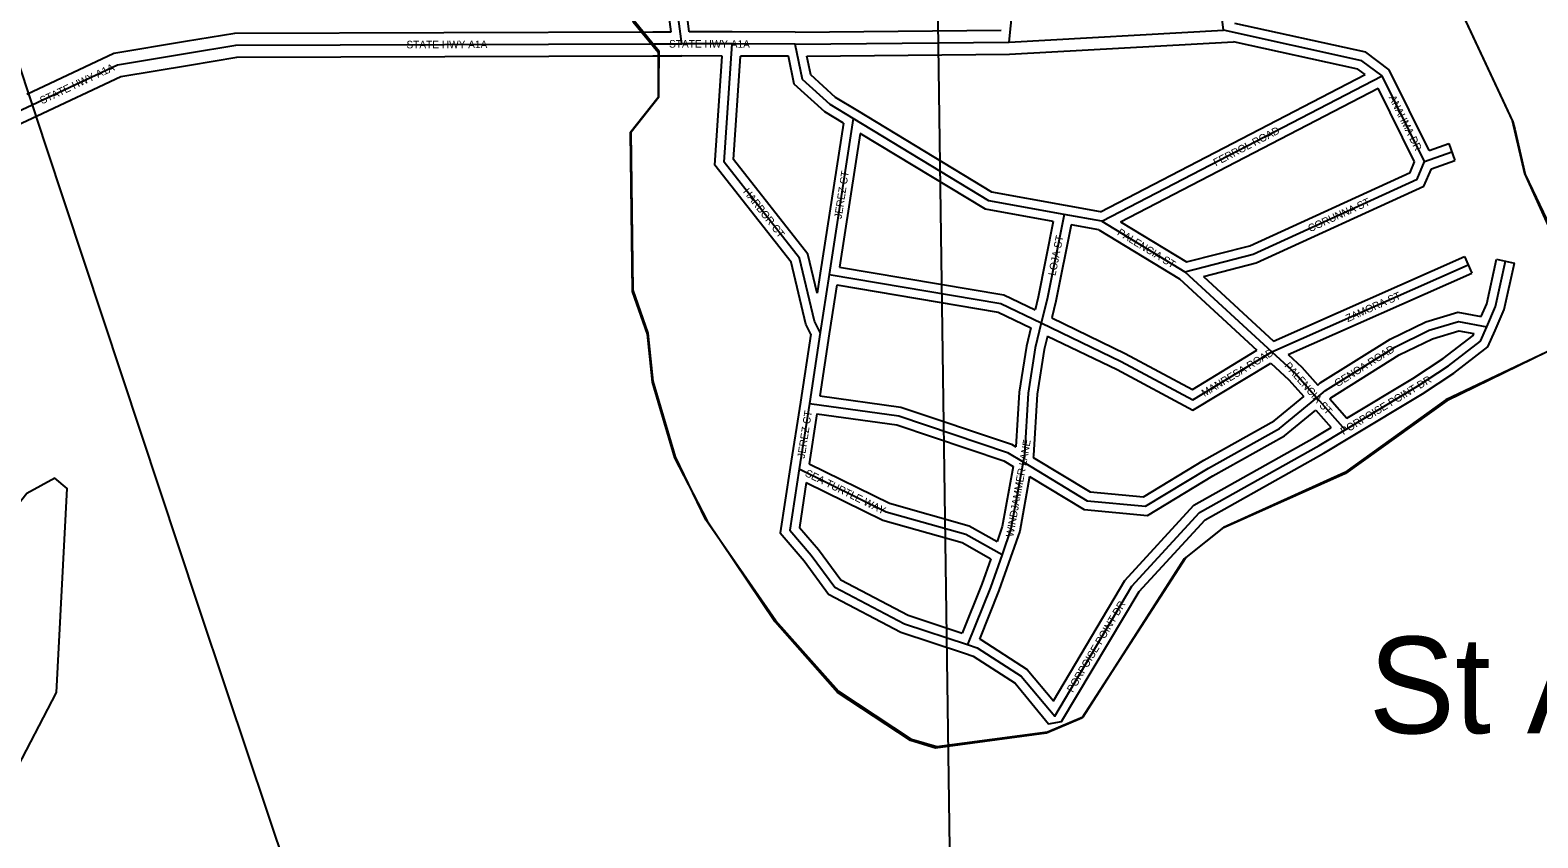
# Model space of a CAD drawing. Extents: x 418523 to 616617, y 1878279 to 2196743.
# Drawn here: x 559594 to 564582, y 2027177 to 2029851 of the extents above; entities that cross this region are included whole.
import ezdxf

# ---------------------------------------------------------------- set-up
doc = ezdxf.new("R2010")
doc.units = 0
for name, color, linetype in [('Level 1', 7, 'Continuous'), ('Level 22', 7, 'Continuous'), ('Level 23', 7, 'Continuous'), ('Level 31', 7, 'Continuous'), ('Level 32', 7, 'Continuous'), ('Level 34', 7, 'Continuous'), ('Level 41', 7, 'Continuous'), ('Level 5', 7, 'Continuous'), ('Level 8', 7, 'Continuous')]:
    doc.layers.add(name, color=color, linetype=linetype)

msp = doc.modelspace()

# ---------------------------------------------------------------- linework, layer by layer
at = {"layer": 'Level 1'}
msp.add_line((562655.833, 2025828.258), (562597.423, 2029956.365), dxfattribs=at)
at = {"layer": 'Level 22'}
for p, q in [((561654.286, 2029805.851), (561749.649, 2029805.97)), ((561916.295, 2029805.539), (561749.649, 2029805.97)), ((562124.76, 2029805.001), (561916.295, 2029805.539)), ((562124.76, 2029805.001), (562833.185, 2029811.549)), ((562833.185, 2029811.549), (563542.01, 2029851.203)), ((559517.02, 2029564.881), (559599.812, 2029603.574))]:
    msp.add_line(p, q, dxfattribs=at)
for points in [[(563542.01, 2029851.203), (563509.44, 2030126.578), (563443.099, 2030326.761)], [(560113.829, 2029774.958), (560273.893, 2029801.812), (561654.286, 2029805.851)], [(559599.812, 2029603.574), (559882.132, 2029736.293), (560113.829, 2029774.958)]]:
    msp.add_lwpolyline(points, dxfattribs=at)
at = {"layer": 'Level 23'}
for p, q in [((561654.237, 2029845.851), (561714.302, 2029845.926)), ((561916.398, 2029845.539), (561774.793, 2029845.905)), ((562124.864, 2029845.001), (561916.398, 2029845.539)), ((562124.864, 2029845.001), (562806.954, 2029851.308)), ((562834.489, 2029771.557), (563575.761, 2029813.026)), ((561654.336, 2029765.851), (561749.546, 2029765.969)), ((561883.575, 2029765.621), (561749.546, 2029765.969)), ((562102.552, 2029765.057), (561943.698, 2029765.466)), ((562163.82, 2029765.359), (562834.489, 2029771.558)), ((559533.956, 2029528.641), (559616.75, 2029567.335))]:
    msp.add_line(p, q, dxfattribs=at)
for points in [[(559582.795, 2029639.775), (559870.106, 2029774.841), (560107.245, 2029814.413)], [(560107.21, 2029814.407), (560270.502, 2029841.803), (561654.169, 2029845.853)], [(560120.447, 2029735.509), (560277.284, 2029761.821), (561654.404, 2029765.851)], [(559616.83, 2029567.373), (559894.159, 2029697.746), (560120.413, 2029735.503)]]:
    msp.add_lwpolyline(points, dxfattribs=at)
at = {"layer": 'Level 31'}
for p, q in [((562833.185, 2029811.549), (562867.66, 2030161.668)), ((563140.26, 2029218.724), (564066.914, 2029699.683)), ((564207.82, 2029416.036), (564066.914, 2029699.683)), ((562317.071, 2029558.308), (562237.809, 2029042.111)), ((564207.82, 2029416.036), (564297.878, 2029448.176)), ((563140.26, 2029218.724), (563014.539, 2029241.227)), ((563140.26, 2029218.724), (563414.84, 2029051.468)), ((563702.165, 2028786.358), (564352.385, 2029074.557)), ((562237.809, 2029042.111), (562208.168, 2028849.81)), ((563414.84, 2029051.468), (563702.165, 2028786.358)), ((562208.168, 2028849.81), (562172.08, 2028614.613)), ((562172.08, 2028614.613), (562138.574, 2028398.321)), ((563850.691, 2028634.336), (563944.522, 2028527.909))]:
    msp.add_line(p, q, dxfattribs=at)
for points in [[(561749.649, 2029805.97), (561725.115, 2029998.046), (561492.915, 2030498.683), (561459.887, 2030590.412), (561468.276, 2030648.94)], [(562208.168, 2028849.81), (562188.939, 2028888.044), (562139.415, 2029096.55), (561890.258, 2029413.941), (561916.295, 2029805.539)], [(562317.071, 2029558.308), (562240.835, 2029604.689), (562149.489, 2029688.202), (562124.76, 2029805.001)], [(564066.914, 2029699.683), (564000.191, 2029750.037), (563542.01, 2029851.203)], [(563014.539, 2029241.227), (562765.314, 2029286.595), (562317.071, 2029558.308)], [(563414.84, 2029051.468), (563639.932, 2029109.084), (564182.644, 2029357.549), (564207.82, 2029416.036)], [(563014.539, 2029241.227), (562958.38, 2028960.623), (562939.487, 2028881.757)], [(564413.334, 2028868.935), (564442.651, 2028936.139), (564475.342, 2029086.249)], [(562237.809, 2029042.111), (562805.95, 2028946.466), (562939.487, 2028881.757)], [(562939.487, 2028881.757), (562919.634, 2028799.256), (562895.805, 2028649.125), (562883.567, 2028446.596), (562879.068, 2028421.516)], [(562939.487, 2028881.757), (563203.714, 2028754.166), (563440.38, 2028627.374), (563702.165, 2028786.358)], [(563850.691, 2028634.336), (563879.901, 2028658.626), (564108.695, 2028802.06), (564222.892, 2028857.412), (564319.598, 2028886.626), (564413.334, 2028868.935)], [(563944.522, 2028527.909), (564184.409, 2028672.406), (564286.913, 2028739.789), (564392.623, 2028821.711), (564413.334, 2028868.935)], [(563702.165, 2028786.358), (563780.241, 2028714.519), (563850.691, 2028634.336)], [(562172.08, 2028614.613), (562468.21, 2028573.85), (562827.82, 2028452.557), (562879.068, 2028421.516)], [(562879.068, 2028421.516), (563091.019, 2028293.329), (563284.24, 2028275.018), (563492.401, 2028401.044), (563727.188, 2028532.458), (563850.691, 2028634.336)], [(562694.713, 2027816.853), (562726.686, 2027806.225), (562872.825, 2027712.026), (562983.698, 2027579.371), (563239.53, 2028010.749), (563462.881, 2028254.199), (563858.848, 2028476.486), (563944.522, 2028527.909)], [(562879.068, 2028421.516), (562838.899, 2028199.784), (562809.534, 2028114.761)], [(562138.574, 2028398.321), (562107.005, 2028195.842), (562178.395, 2028112.742)], [(562138.574, 2028398.321), (562426.21, 2028256.481), (562689.625, 2028182.346), (562809.534, 2028114.761)], [(562178.395, 2028112.742), (562255.75, 2028007.446), (562486.729, 2027886.116), (562694.713, 2027816.853)], [(562809.534, 2028114.761), (562771.236, 2028006.125), (562694.713, 2027816.853)]]:
    msp.add_lwpolyline(points, dxfattribs=at)
at = {"layer": 'Level 32'}
for p, q in [((563135.5, 2029250.053), (564010.869, 2029704.393)), ((564222.833, 2029453.247), (564090.635, 2029719.366)), ((563201.36, 2029216.635), (564053.631, 2029658.987)), ((564174.77, 2029415.133), (564053.631, 2029658.987)), ((562284.381, 2029543.08), (562208.156, 2029046.664)), ((562339.911, 2029509.381), (562271.951, 2029066.786)), ((564222.833, 2029453.246), (564287.795, 2029476.43)), ((564287.795, 2029476.43), (564307.962, 2029419.92)), ((564230.21, 2029392.171), (564307.962, 2029419.92)), ((563135.5, 2029250.053), (563019.825, 2029270.758)), ((563129.449, 2029190.181), (563038.188, 2029206.516)), ((563201.36, 2029216.634), (563419.651, 2029083.666)), ((563129.449, 2029190.181), (563396.688, 2029027.397)), ((563708.026, 2028821.771), (564340.229, 2029101.985)), ((564340.229, 2029101.985), (564364.543, 2029047.13)), ((564446.029, 2029092.633), (564504.655, 2029079.865)), ((562208.159, 2029046.681), (562197.902, 2028980.133)), ((562262.826, 2029007.476), (562237.819, 2028845.239)), ((563396.689, 2029027.396), (563652.545, 2028791.322)), ((563475.748, 2029036.09), (563708.025, 2028821.77)), ((563756.14, 2028777.465), (564364.543, 2029047.13)), ((562177.062, 2028844.889), (562142.426, 2028619.163)), ((562237.822, 2028845.259), (562206.355, 2028640.178)), ((562142.433, 2028619.206), (562108.927, 2028402.912)), ((563893.617, 2028631.013), (563950.478, 2028566.519)), ((562197.211, 2028580.869), (562171.593, 2028415.488)), ((563847.388, 2028592.718), (563898.195, 2028535.091))]:
    msp.add_line(p, q, dxfattribs=at)
for points in [[(561714.302, 2029845.926), (561695.945, 2029989.637), (561465.14, 2030487.267), (561429.13, 2030587.276), (561441.239, 2030671.751)], [(561774.793, 2029845.905), (561754.285, 2030006.455), (561520.69, 2030510.099), (561490.643, 2030593.549), (561495.315, 2030626.127)], [(564090.635, 2029719.367), (564013.045, 2029777.922), (563579.639, 2029873.617)], [(564010.868, 2029704.393), (563987.338, 2029722.152), (563575.761, 2029813.026)], [(562177.062, 2028844.889), (562160.561, 2028877.698), (562111.75, 2029083.207), (561859.56, 2029404.46), (561883.575, 2029765.621)], [(562197.902, 2028980.133), (562167.082, 2029109.892), (561920.955, 2029423.423), (561943.698, 2029765.466)], [(562284.381, 2029543.079), (562222.748, 2029580.576), (562122.135, 2029672.562), (562102.552, 2029765.057)], [(562332.665, 2029583.938), (562258.923, 2029628.801), (562176.844, 2029703.842), (562163.82, 2029765.358)], [(563019.912, 2029270.743), (562776.132, 2029315.119), (562332.623, 2029583.963)], [(562979.13, 2029217.179), (562754.495, 2029258.071), (562339.911, 2029509.381)], [(563419.65, 2029083.666), (563629.888, 2029137.481), (564159.654, 2029380.02), (564174.77, 2029415.134)], [(563475.748, 2029036.09), (563649.976, 2029080.686), (564205.634, 2029335.079), (564230.21, 2029392.171)], [(562979.131, 2029217.179), (562929.073, 2028967.064), (562919.002, 2028925.021)], [(563038.188, 2029206.516), (562987.686, 2028954.183), (562974.292, 2028898.265)], [(562271.951, 2029066.786), (562815.167, 2028975.338), (562919.002, 2028925.021)], [(564395.399, 2028902.85), (564413.968, 2028945.418), (564446.029, 2029092.633)], [(564440.832, 2028856.939), (564471.335, 2028926.859), (564504.655, 2029079.865)], [(562262.827, 2029007.476), (562796.735, 2028917.595), (562904.668, 2028865.291)], [(563853.959, 2028676.07), (563862.264, 2028682.978), (564094.142, 2028828.346), (564211.943, 2028885.445), (564317.949, 2028917.467), (564395.399, 2028902.85)], [(562904.669, 2028865.292), (562890.189, 2028805.126), (562865.947, 2028652.389), (562854.997, 2028471.171)], [(562974.292, 2028898.265), (563217.325, 2028780.908), (563439.448, 2028661.908), (563652.545, 2028791.322)], [(563960.002, 2028502.211), (564200.395, 2028647.011), (564304.368, 2028715.361), (564417.032, 2028802.672), (564440.808, 2028856.885)], [(562959.95, 2028838.56), (562949.079, 2028793.386), (562925.664, 2028645.861), (562913.407, 2028443.03), (562912.24, 2028436.514)], [(562959.95, 2028838.56), (563190.101, 2028727.423), (563441.313, 2028592.84), (563698.455, 2028749.004)], [(563893.618, 2028631.013), (563897.539, 2028634.276), (564123.249, 2028775.775), (564233.841, 2028829.381), (564321.247, 2028855.785), (564370.714, 2028846.448)], [(563950.479, 2028566.518), (564168.423, 2028697.799), (564269.458, 2028764.216), (564368.214, 2028840.749), (564370.714, 2028846.447)], [(563756.14, 2028777.465), (563801.727, 2028735.517), (563853.959, 2028676.071)], [(563698.455, 2028749.004), (563758.755, 2028693.521), (563807.727, 2028637.784)], [(562206.355, 2028640.177), (562475.11, 2028603.183), (562840.538, 2028479.929), (562854.997, 2028471.171)], [(562912.239, 2028436.514), (563100.676, 2028322.549), (563277.191, 2028305.821), (563477.301, 2028426.972), (563710.18, 2028557.319), (563807.727, 2028637.784)], [(562197.212, 2028580.869), (562461.31, 2028544.516), (562815.102, 2028425.186), (562845.869, 2028406.55)], [(562900.822, 2028373.297), (563081.362, 2028264.109), (563291.29, 2028244.216), (563507.501, 2028375.115), (563744.196, 2028507.598), (563847.388, 2028592.718)], [(562734.508, 2027835.239), (562739.75, 2027833.497), (562892.917, 2027734.769), (562979.523, 2027631.146), (563215.315, 2028028.734), (563444.015, 2028278.013), (563843.782, 2028502.432), (563898.195, 2028535.091)], [(562685.25, 2027788.384), (562713.623, 2027778.952), (562852.734, 2027689.284), (562963.022, 2027554.69), (563006.395, 2027562.581), (563263.745, 2027992.765), (563481.747, 2028230.386), (563873.914, 2028450.538), (563959.962, 2028502.186)], [(562171.593, 2028415.488), (562437, 2028284.611), (562701.22, 2028210.249), (562792.923, 2028158.561)], [(562108.931, 2028402.942), (562075.23, 2028186.79), (562154.895, 2028094.06)], [(562845.868, 2028406.549), (562809.79, 2028207.4), (562792.923, 2028158.561)], [(562900.822, 2028373.298), (562868.008, 2028192.168), (562837.89, 2028104.967)], [(562161.928, 2028353.354), (562138.779, 2028204.894), (562201.897, 2028131.424)], [(562161.927, 2028353.354), (562415.422, 2028228.351), (562678.032, 2028154.443), (562772.87, 2028100.988)], [(562201.897, 2028131.425), (562275.829, 2028030.786), (562498.521, 2027913.81), (562677.461, 2027854.217)], [(562154.895, 2028094.058), (562235.67, 2027984.106), (562474.936, 2027858.424), (562685.235, 2027788.389)], [(562772.87, 2028100.988), (562743.168, 2028016.74), (562677.461, 2027854.218)], [(562837.828, 2028104.786), (562799.305, 2027995.51), (562734.508, 2027835.239)]]:
    msp.add_lwpolyline(points, dxfattribs=at)
at = {"layer": 'Level 5'}
for points in [[(562644.5, 2034084.822), (562867.655, 2033483.891), (563306.184, 2032465.413), (563322.536, 2032365.351), (563347.507, 2032356.911), (563355.559, 2032265.179), (563488.116, 2032006.325), (563512.799, 2031906.223), (563570.832, 2031805.991), (563859.436, 2030829.692), (564099.82, 2030403.756), (564497.224, 2029552.171), (564538.348, 2029376.977), (564621.123, 2029193.284)], [(561531.075, 2030053.598), (561588.88, 2029878.374), (561671.914, 2029778.043), (561671.426, 2029627.99), (561579.336, 2029511.576), (561585.975, 2028986.384), (561635.54, 2028844.501), (561651.723, 2028686.048), (561725.929, 2028435.723), (561833.615, 2028226.96), (562057.626, 2027892.785), (562265.285, 2027658.681)], [(564820.183, 2028884.219), (564277.505, 2028627.527), (563943.271, 2028386.848), (563542.535, 2028204.759), (563417.165, 2028105.116), (563073.645, 2027572.699), (562956.774, 2027523.076), (562589.806, 2027474.231), (562506.544, 2027499.501), (562265.285, 2027658.681)], [(559681.015, 2027658.711), (559716.544, 2028333.857), (559674.962, 2028367.337), (559583.09, 2028317.616), (559524.48, 2028242.783)], [(559114.5, 2027777.257), (559297.118, 2027526.574), (559355.041, 2027401.331), (559463.285, 2027359.292), (559538.376, 2027384.073), (559681.015, 2027658.711)]]:
    msp.add_lwpolyline(points, dxfattribs=at)
at = {"layer": 'Level 8'}
for points in [[(562635.86, 2034089.092), (562867.875, 2033488.081), (563306.904, 2032469.063), (563323.906, 2032369.061), (563348.907, 2032353.061), (563356.909, 2032261.059), (563489.916, 2032002.055), (563513.919, 2031902.053), (563571.922, 2031802.051), (563706.933, 2031348.042), (563793.94, 2031054.036), (563860.946, 2030826.032), (563897.948, 2030761.031), (564101.96, 2030400.026), (564499.984, 2029548.011), (564505.985, 2029523.011), (564540.988, 2029373.007), (564623.993, 2029198.004)], [(559393.852, 2030224.966), (559599.868, 2029603.955), (559644.871, 2029468.952), (560148.91, 2027947.923), (560244.918, 2027660.918), (560643.948, 2026468.896)], [(562959.984, 2027526.946), (562593.976, 2027477.941), (562509.974, 2027502.941), (562268.965, 2027661.941), (562060.956, 2027895.945), (561828.945, 2028229.95), (561728.939, 2028438.953), (561654.933, 2028688.958), (561638.93, 2028847.961), (561588.925, 2028989.964), (561581.916, 2029514.976), (561673.916, 2029630.98), (561673.915, 2029668.981), (561674.914, 2029780.983), (561653.913, 2029805.983), (561591.91, 2029881.985)], [(564803.003, 2028878.999), (564280.995, 2028623.987), (563945.991, 2028382.978), (563537.985, 2028200.969), (563411.984, 2028100.965), (563076.985, 2027576.949), (562959.984, 2027526.946)]]:
    msp.add_lwpolyline(points, dxfattribs=at)

# ---------------------------------------------------------------- texts
at = {"layer": 'Level 34'}
for s, height, rotation, p in [('STATE HWY A1A', 24.99916, 0.167003, (560838.856, 2029790.967)), ('STATE HWY A1A', 25, 359.851386, (561707.665, 2029793.579)), ('STATE HWY A1A', 24.99916, 25.177567, (559632.92, 2029605.328)), ('ANAHMA DR', 24.9992, 296.415628, (564088.343, 2029628.453)), ('FERROL ROAD', 25, 27.429886, (563516.674, 2029400.011)), ('JEREZ CT', 25, 81.269417, (562278.607, 2029225.466)), ('HARBOR CT', 25, 308.131625, (561951.328, 2029315.906)), ('CORUNNA ST', 25, 24.598658, (563828.86, 2029181.833)), ('LOJA ST', 25, 78.681706, (562986.292, 2029036.396)), ('PALENCIA ST', 25, 328.652297, (563188.334, 2029174.806)), ('ZAMORA ST', 25, 23.903814, (563953.299, 2028883.999)), ('MANRESA ROAD', 25, 31.269872, (563479.231, 2028636.346)), ('GENOA ROAD', 25, 32.083206, (563919.278, 2028668.563)), ('PALENCIA ST', 25, 311.302169, (563742.152, 2028738.935)), ('PORPOISE POINT DR', 25, 31.062078, (563938.983, 2028509.983)), ('JEREZ CT', 25, 81.193392, (562156.395, 2028431.721)), ('WINDJAMMER LANE', 25, 79.730658, (562846.52, 2028171.749)), ('SEA TURTLE WAY', 25, 333.750339, (562155.255, 2028376.16)), ('PORPOISE POINT DR', 25, 59.328717, (563043.8, 2027656.214))]:
    msp.add_text(s, height=height, rotation=rotation, dxfattribs=at).set_placement(p)
at = {"layer": 'Level 41'}
msp.add_text('St Augustine Inlet', height=320, dxfattribs=at).set_placement((564022.64, 2027523.111))

doc.saveas('drawing.dxf')
